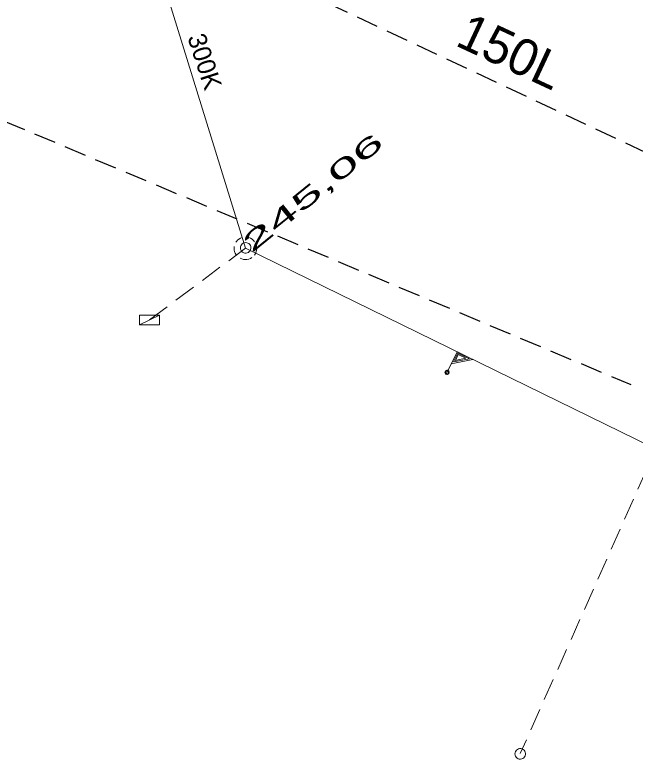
# Model space of a CAD drawing. Extents: x -735085 to -733500, y -1044153 to -1043402.
# Drawn here: x -734812.09 to -734784.97, y -1043591 to -1043558.45 of the extents above; entities that cross this region are included whole.
import ezdxf

# ---------------------------------------------------------------- set-up
doc = ezdxf.new("R2010")
doc.units = 0
doc.header["$LTSCALE"] = 0.32
doc.linetypes.add('MEDIUM_DASHED', pattern=[4.5, 3, -1.5])
doc.layers.add('15', color=7, linetype='Continuous')
doc.layers.add('16', color=7, linetype='Continuous')
for name, color, linetype, lineweight in [('18', 7, 'Continuous', 13), ('20', 7, 'Continuous', 13), ('49', 7, 'Continuous', 13), ('8', 7, 'Continuous', 13)]:
    doc.layers.add(name, color=color, linetype=linetype, lineweight=lineweight)

msp = doc.modelspace()

# ---------------------------------------------------------------- linework, layer by layer
at = {"layer": '18'}
msp.add_line((-734806.641, -1043572), (-734805.767, -1043571.588), dxfattribs=at)
for points in [[(-734802.153, -1043568.187), (-734802.224, -1043568.215), (-734802.291, -1043568.254), (-734802.351, -1043568.302), (-734802.402, -1043568.359), (-734802.426, -1043568.393)], [(-734801.612, -1043568.37), (-734801.662, -1043568.312), (-734801.72, -1043568.262), (-734801.785, -1043568.221), (-734801.856, -1043568.192), (-734801.905, -1043568.178)], [(-734801.617, -1043568.956), (-734801.576, -1043568.891), (-734801.545, -1043568.821), (-734801.526, -1043568.746), (-734801.518, -1043568.67), (-734801.523, -1043568.593), (-734801.529, -1043568.558)], [(-734802.498, -1043568.579), (-734802.504, -1043568.656), (-734802.499, -1043568.733), (-734802.482, -1043568.808), (-734802.453, -1043568.879), (-734802.413, -1043568.945), (-734802.397, -1043568.967)], [(-734802.24, -1043569.096), (-734802.17, -1043569.127), (-734802.095, -1043569.146), (-734802.019, -1043569.153), (-734801.942, -1043569.148), (-734801.867, -1043569.131), (-734801.795, -1043569.103), (-734801.735, -1043569.068)], [(-734793.235, -1043574.17), (-734792.753, -1043573.187), (-734792.062, -1043573.526), (-734793.008, -1043573.706)], [(-734792.911, -1043573.622), (-734792.728, -1043573.249), (-734792.22, -1043573.498), (-734792.911, -1043573.623)], [(-734792.832, -1043573.567), (-734792.703, -1043573.305), (-734792.369, -1043573.469), (-734792.833, -1043573.567)]]:
    msp.add_lwpolyline(points, dxfattribs=at)
for points in [[(-734801.769, -1043568.639), (-734801.775, -1043568.587), (-734801.793, -1043568.537), (-734801.821, -1043568.493), (-734801.859, -1043568.456), (-734801.904, -1043568.429), (-734801.954, -1043568.413), (-734802.006, -1043568.408), (-734802.058, -1043568.415), (-734802.107, -1043568.434), (-734802.151, -1043568.464), (-734802.186, -1043568.503), (-734802.212, -1043568.548), (-734802.227, -1043568.599), (-734802.23, -1043568.651), (-734802.222, -1043568.703), (-734802.201, -1043568.751), (-734802.171, -1043568.794), (-734802.131, -1043568.829), (-734802.085, -1043568.853), (-734802.034, -1043568.867), (-734801.982, -1043568.869), (-734801.93, -1043568.859), (-734801.882, -1043568.837), (-734801.84, -1043568.805), (-734801.807, -1043568.765), (-734801.783, -1043568.718), (-734801.771, -1043568.667)], [(-734806.645, -1043571.588), (-734805.771, -1043571.588), (-734805.771, -1043572), (-734806.645, -1043572)], [(-734793.11, -1043574.127), (-734793.101, -1043574.095), (-734793.103, -1043574.061), (-734793.117, -1043574.031), (-734793.141, -1043574.008), (-734793.172, -1043573.994), (-734793.205, -1043573.992), (-734793.238, -1043574.002), (-734793.264, -1043574.022), (-734793.282, -1043574.051), (-734793.288, -1043574.083), (-734793.284, -1043574.117), (-734793.267, -1043574.146), (-734793.242, -1043574.167), (-734793.21, -1043574.179), (-734793.176, -1043574.179), (-734793.146, -1043574.166), (-734793.12, -1043574.144)], [(-734793.133, -1043574.114), (-734793.127, -1043574.087), (-734793.131, -1043574.059), (-734793.147, -1043574.036), (-734793.171, -1043574.021), (-734793.2, -1043574.017), (-734793.226, -1043574.027), (-734793.248, -1043574.045), (-734793.259, -1043574.071), (-734793.259, -1043574.098), (-734793.247, -1043574.124), (-734793.227, -1043574.143), (-734793.2, -1043574.152), (-734793.171, -1043574.148), (-734793.148, -1043574.134)]]:
    msp.add_lwpolyline(points, close=True, dxfattribs=at)
at = {"layer": '20'}
for p, q in [((-734808.92, -1043546.33), (-734802, -1043568.65)), ((-734808.92, -1043546.33), (-734802, -1043568.65)), ((-734802, -1043568.65), (-734767.879, -1043585.38)), ((-734802, -1043568.65), (-734767.879, -1043585.38))]:
    msp.add_line(p, q, dxfattribs=at)
at = {"layer": '49', "linetype": 'MEDIUM_DASHED'}
msp.add_line((-734806.199, -1043571.79), (-734802, -1043568.65), dxfattribs=at)
msp.add_line((-734806.199, -1043571.79), (-734802, -1043568.65), dxfattribs=at)
at = {"layer": '8', "linetype": 'MEDIUM_DASHED'}
msp.add_line((-734783.287, -1043575.682), (-734789.993, -1043590.765), dxfattribs=at)
at = {"layer": '8', "linetype": 'MEDIUM_DASHED', "lineweight": 25}
for points in [[(-734804.892, -1043550.168), (-734802.34, -1043556.09), (-734769.804, -1043571.373), (-734765.02, -1043573.62)], [(-734842.335, -1043550.559), (-734817.864, -1043560.858), (-734785.16, -1043574.621)]]:
    msp.add_lwpolyline(points, dxfattribs=at)
at = {"layer": '8'}
msp.add_lwpolyline([(-734790.206, -1043590.676), (-734790.222, -1043590.726), (-734790.227, -1043590.779), (-734790.22, -1043590.831), (-734790.201, -1043590.88), (-734790.171, -1043590.923), (-734790.132, -1043590.959), (-734790.087, -1043590.985), (-734790.037, -1043591.001), (-734789.985, -1043591.004), (-734789.932, -1043590.995), (-734789.884, -1043590.974), (-734789.842, -1043590.945), (-734789.807, -1043590.905), (-734789.782, -1043590.859), (-734789.768, -1043590.808), (-734789.766, -1043590.756), (-734789.776, -1043590.704), (-734789.797, -1043590.655), (-734789.829, -1043590.614), (-734789.869, -1043590.58), (-734789.916, -1043590.557), (-734789.967, -1043590.544), (-734790.02, -1043590.544), (-734790.072, -1043590.555), (-734790.118, -1043590.578), (-734790.16, -1043590.61), (-734790.192, -1043590.652)], close=True, dxfattribs=at)

# ---------------------------------------------------------------- texts
at = {"layer": '15'}
msp.add_text('150L', height=1.6, rotation=335, dxfattribs=at).set_placement((-734792.887, -1043559.764))
at = {"layer": '16'}
msp.add_text('300K', height=0.8, rotation=288, dxfattribs=at).set_placement((-734804.553, -1043559.423))
at = {"layer": '16', "width": 2.3}
msp.add_text('245,06', height=0.8, rotation=39, dxfattribs=at).set_placement((-734801.74, -1043568.89))

doc.saveas('drawing.dxf')
